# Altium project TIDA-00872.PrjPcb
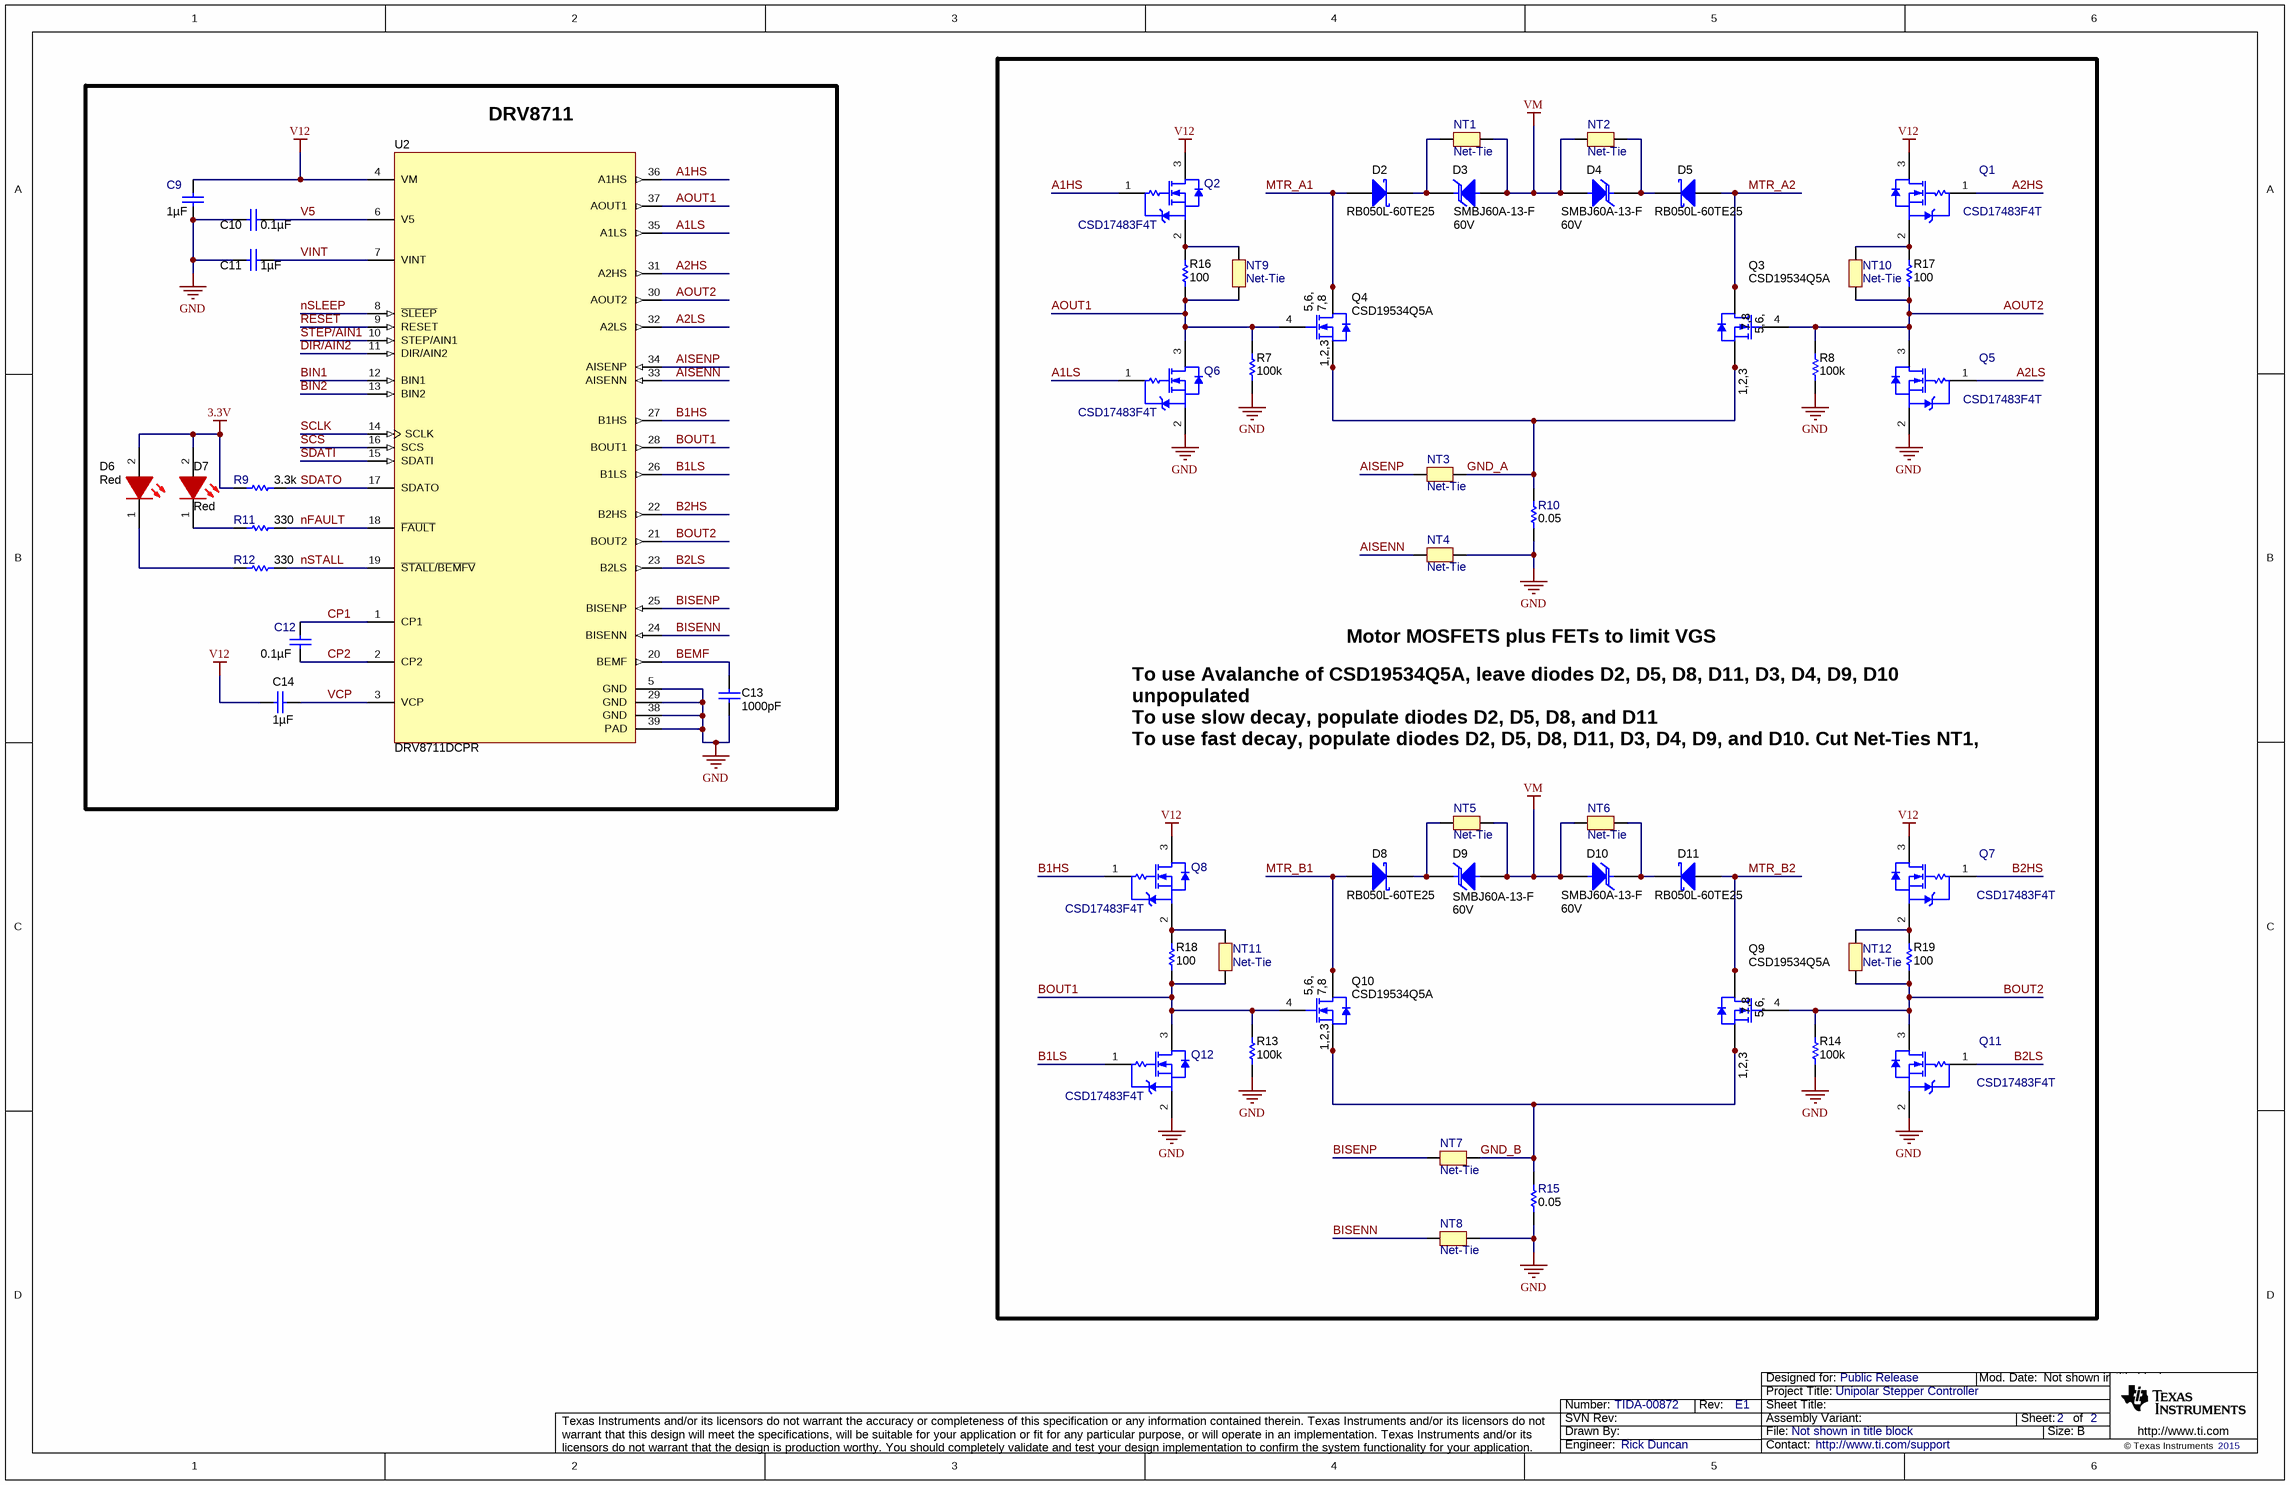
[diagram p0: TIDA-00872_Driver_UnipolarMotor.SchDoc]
CopyrightYear: 2015; EVM_Orderable: N/A; PCB_Layout: Fabio Fernades; PCB_Rev: E1; PRJ_Customer: Public Release; PRJ_Engineer: Rick Duncan; PRJ_Number: TIDA-00872; PRJ_Title: Unipolar Stepper Controller; SCH_Rev: E1; TechSupport: http://www.ti.com/support; TID: TIDA-00872
2 sheets, 82 parts. Net scope: global (net labels, ports and power ports of the same name join across sheets).
Board file: TIDA-00872.PcbDoc
Sheets:
  TIDA-00872_Driver_UnipolarMotor.SchDoc
  TIDA-00872_Unipolar.SchDoc

## Sheet TIDA-00872_Driver_UnipolarMotor.SchDoc
size 431 x 279 mm; Date: Not shown in title block; ApprovedBy: Not shown in title block; CheckedBy: Not shown in title block; Author: Not shown in title block; CompanyName: Not shown in title block; Engineer: Not shown in title block; Organization: Not shown in title block; Address1: Not shown in title block; Address2: Not shown in title block; Address3: Not shown in title block; Address4: Not shown in title block; DocumentNumber: 1; Revision: Use project parameter SCH_Rev; SheetNumber: 2; SheetTotal: 2; PageSetup: Record=PageOptions¦CenterHorizontal=True¦CenterVertical=True¦PrintScale=1.00¦XCorrection=1.00¦YCorrection=1.00¦PrintKind=0¦BorderSize=5000000¦LeftOffset=0¦BottomOffset=0¦Orientation=2¦PaperLength=1000¦PaperWidth=1000¦Scale=100¦PaperSource=15¦PrintQuality=600¦MediaType=1¦DitherType=10¦PaperKind=Letter¦PrintScaleMode=1

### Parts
C9  ValueDisplayed: 1µF  [1206L]  (hidden comment: HMK316B7105KL-T)
C10  ValueDisplayed: 0.1µF  [0603_095]  (hidden comment: 885012206071)
C11  ValueDisplayed: 1µF  [0603_095]  (hidden comment: 885012206052)
C12  ValueDisplayed: 0.1µF  [0603L]  (hidden comment: GRM188R72A104KA35D)
C13  ValueDisplayed: 1000pF  [0603_095]  (hidden comment: 885012206034)
C14  ValueDisplayed: 1µF  [0805_140]  (hidden comment: 885012207103)
D2  RB050L-60TE25  [SMA]
D3  SMBJ60A-13-F  value 60V  [SMB]
D4  SMBJ60A-13-F  value 60V  [SMB]
D5  RB050L-60TE25  [SMA]
D6  value Red  [WL-SMCW_RED_0805]  (hidden comment: 150080SS75000)
D7  value Red  [WL-SMCW_RED_0805]  (hidden comment: 150080SS75000)
D8  RB050L-60TE25  [SMA]
D9  SMBJ60A-13-F  value 60V  [SMB]
D10  SMBJ60A-13-F  value 60V  [SMB]
D11  RB050L-60TE25  [SMA]
NT1  Net-Tie  [Net-Tie_20milWide_60milLong]  (net tie, no BOM)
NT2  Net-Tie  [Net-Tie_20milWide_60milLong]  (net tie, no BOM)
NT3  Net-Tie  [Net-Tie_10mil]  (net tie, no BOM)
NT4  Net-Tie  [Net-Tie_10mil]  (net tie, no BOM)
NT5  Net-Tie  [Net-Tie_20milWide_60milLong]  (net tie, no BOM)
NT6  Net-Tie  [Net-Tie_20milWide_60milLong]  (net tie, no BOM)
NT7  Net-Tie  [Net-Tie_10mil]  (net tie, no BOM)
NT8  Net-Tie  [Net-Tie_10mil]  (net tie, no BOM)
NT9  Net-Tie  [Net-Tie_10mil]  (net tie, no BOM)
NT10  Net-Tie  [Net-Tie_10mil]  (net tie, no BOM)
NT11  Net-Tie  [Net-Tie_10mil]  (net tie, no BOM)
NT12  Net-Tie  [Net-Tie_10mil]  (net tie, no BOM)
Q1  CSD17483F4T  [YJC0003A]
Q2  CSD17483F4T  [YJC0003A]
Q3  CSD19534Q5A  [TRANS_NexFET_Q5A]
Q4  CSD19534Q5A  [TRANS_NexFET_Q5A]
Q5  CSD17483F4T  [YJC0003A]
Q6  CSD17483F4T  [YJC0003A]
Q7  CSD17483F4T  [YJC0003A]
Q8  CSD17483F4T  [YJC0003A]
Q9  CSD19534Q5A  [TRANS_NexFET_Q5A]
Q10  CSD19534Q5A  [TRANS_NexFET_Q5A]
Q11  CSD17483F4T  [YJC0003A]
Q12  CSD17483F4T  [YJC0003A]
R7  ValueDisplayed: 100k  [0402L]  (hidden comment: CRCW0402100KFKED)
R8  ValueDisplayed: 100k  [0402L]  (hidden comment: CRCW0402100KFKED)
R9  value 3.3k  [0603L]  (hidden comment: CRCW06033K30JNEA)
R10  value 0.05  [2512L]  (hidden comment: CRA2512-FZ-R050ELF)
R11  value 330  [0603L]  (hidden comment: CRCW0603330RJNEA)
R12  value 330  [0603L]  (hidden comment: CRCW0603330RJNEA)
R13  ValueDisplayed: 100k  [0402L]  (hidden comment: CRCW0402100KFKED)
R14  ValueDisplayed: 100k  [0402L]  (hidden comment: CRCW0402100KFKED)
R15  value 0.05  [2512L]  (hidden comment: CRA2512-FZ-R050ELF)
R16  ValueDisplayed: 100  [0805L]  (hidden comment: CRCW0805100RFKEA)
R17  ValueDisplayed: 100  [0805L]  (hidden comment: CRCW0805100RFKEA)
R18  ValueDisplayed: 100  [0805L]  (hidden comment: CRCW0805100RFKEA)
R19  ValueDisplayed: 100  [0805L]  (hidden comment: CRCW0805100RFKEA)
U2  DRV8711DCPR  [DCP0038A_N]

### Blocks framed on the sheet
DRV8711: C9-C14 D6 D7 R9 R11 R12 U2
Motor MOSFETS plus FETs to limit VGS: D2-D5 D8-D11 NT1-NT12 Q1-Q12 R7 R8 R10 R13-R19

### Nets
3.3V: D6.2(A) D7.2(A) R9.2
GND: C9.2 C10.2 C11.2 C13.2 NT4.2 NT8.1 Q5.2(S) Q6.2(S) Q11.2(S) Q12.2(S) R7.1 R8.1 R10.1 R13.1 R14.1 R15.1 U2.5(GND) U2.29(GND) U2.38(GND) U2.39(PAD)
V12: C9.1 C14.2 Q1.3(D) Q2.3(D) Q7.3(D) Q8.3(D) U2.4(VM)
VM: D3.2(A) D4.2(A) D9.2(A) D10.2(A) NT1.2 NT2.1 NT5.2 NT6.1
A1HS: Q2.1(G) U2.36(A1HS)
A1LS: Q6.1(G) U2.35(A1LS)
A2HS: Q1.1(G) U2.31(A2HS)
A2LS: Q5.1(G) U2.32(A2LS)
AISENN: NT4.1 U2.33(AISENN)
AISENP: NT3.1 U2.34(AISENP)
AOUT1: NT9.1 Q4.4(G) Q6.3(D) R7.2 R16.1 U2.37(AOUT1)
AOUT2: NT10.1 Q3.4(G) Q5.3(D) R8.2 R17.1 U2.30(AOUT2)
B1HS: Q8.1(G) U2.27(B1HS)
B1LS: Q12.1(G) U2.26(B1LS)
B2HS: Q7.1(G) U2.22(B2HS)
B2LS: Q11.1(G) U2.23(B2LS)
BEMF: C13.1 U2.20(BEMF)
BIN1: U2.12(BIN1)
BIN2: U2.13(BIN2)
BISENN: NT8.2 U2.24(BISENN)
BISENP: NT7.2 U2.25(BISENP)
BOUT1: NT11.1 Q10.4(G) Q12.3(D) R13.2 R18.1 U2.28(BOUT1)
BOUT2: NT12.1 Q9.4(G) Q11.3(D) R14.2 R19.1 U2.21(BOUT2)
CP1: C12.1 U2.1(CP1)
CP2: C12.2 U2.2(CP2)
DIR/AIN2: U2.11(DIR/AIN2)
GND_A: NT3.2 Q3.1(S) Q3.2(S) Q3.3(S) Q4.1(S) Q4.2(S) Q4.3(S) R10.2
GND_B: NT7.1 Q9.1(S) Q9.2(S) Q9.3(S) Q10.1(S) Q10.2(S) Q10.3(S) R15.2
MTR_A1: D2.2(A) Q4.5(D) Q4.6(D) Q4.7(D) Q4.8(D) Q4.9(D)
MTR_A2: D5.2(A) Q3.5(D) Q3.6(D) Q3.7(D) Q3.8(D) Q3.9(D)
MTR_B1: D8.2(A) Q10.5(D) Q10.6(D) Q10.7(D) Q10.8(D) Q10.9(D)
MTR_B2: D11.2(A) Q9.5(D) Q9.6(D) Q9.7(D) Q9.8(D) Q9.9(D)
nFAULT: R11.2 U2.18(~{FAULT})
nSLEEP: U2.8(~{SLEEP})
nSTALL: R12.1 U2.19(~{STALL}/~{BEMFV})
RESET: U2.9(RESET)
SCLK: U2.14(SCLK)
SCS: U2.16(SCS)
SDATI: U2.15(SDATI)
SDATO: R9.1 U2.17(SDATO)
STEP/AIN1: U2.10(STEP/AIN1)
V5: C10.1 U2.6(V5)
VCP: C14.1 U2.3(VCP)
VINT: C11.1 U2.7(VINT)
NetD2_1: D2.1(K) D3.1(K) NT1.1
NetD4_1: D4.1(K) D5.1(K) NT2.2
NetD6_1: D6.1(K) R12.2
NetD7_1: D7.1(K) R11.1
NetD8_1: D8.1(K) D9.1(K) NT5.1
NetD10_1: D10.1(K) D11.1(K) NT6.2
NetNT9_2: NT9.2 Q2.2(S) R16.2
NetNT10_2: NT10.2 Q1.2(S) R17.2
NetNT11_2: NT11.2 Q8.2(S) R18.2
NetNT12_2: NT12.2 Q7.2(S) R19.2

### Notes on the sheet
- To use Avalanche of CSD19534Q5A, leave diodes D2, D5, D8, D11, D3, D4, D9, D10 unpopulated
  To use slow decay, populate diodes D2, D5, D8, and D11
  To use fast decay, populate diodes D2, D5, D8, D11, D3, D4, D9, and D10. Cut Net-Ties NT1, NT2, NT5, and NT6 on bottom of PCB

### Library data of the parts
C9 = GRM31CR72A105KA01L: CAP CER 1UF 100V 10% X7R 1206; Manufacturer: Taiyo Yuden; Polarized: N; CompType: Capacitor; U/M: EA; Cap_F: 0.000001; Tolerance_%: 10; Value1: Unknown; VDC_V: 100; TaMin_C: -55; TaMax_C: 125; Cap_Case: 2220
C10 = 885012206071: CAP, CERM, 0.1 µF, 25 V, +/- 10%, X7R, 0603; Manufacturer: Wurth Elektronik; Polarized: N; CompType: Capacitor; Value: 0.1uF; U/M: EA; Cap_F: 0.0000001; Tolerance_%: 10; Value1: Unknown; VDC_V: 25; Value2: 25V; TaMin_C: -55; TaMax_C: 125; Cap_Case: 0603; AEC Category: Q200
C11 = 885012206052: CAP, CERM, 1 µF, 16 V, +/- 10%, X7R, 0603; Manufacturer: Wurth Elektronik; Polarized: N; CompType: Capacitor; Value: 1uF; U/M: EA; Cap_F: 0.000001; Tolerance_%: 10; Value1: Unknown; VDC_V: 16; Value2: 16V; TaMin_C: -55; TaMax_C: 125; Cap_Case: 0603; AEC Category: Q200
C12 = GRM188R72A104KA35D: CAP, CERM, 0.1uF, 100V, +/-10%, X7R, 0603; Manufacturer: MuRata; Polarized: N; CompType: Capacitor; U/M: EA; Cap_F: 0.0000001; Tolerance_%: 10; Value1: Unknown; VDC_V: 100; TaMin_C: -55; TaMax_C: 125; Cap_Case: 0603
C13 = 885012206034: CAP, CERM, 1000 pF, 16 V, +/- 10%, X7R, 0603; Manufacturer: Wurth Elektronik; Polarized: N; CompType: Capacitor; Value: 1000pF; U/M: EA; Cap_F: 0.000000001; Tolerance_%: 10; Value1: Unknown; VDC_V: 16; Value2: 16V; TaMin_C: -55; TaMax_C: 125; Cap_Case: 0603; AEC Category: Q200
C14 = 885012207103: CAP, CERM, 1 µF, 50 V, +/- 10%, X7R, 0805_140; Manufacturer: Wurth Elektronik; Polarized: N; CompType: Capacitor; Value: 1uF; U/M: EA; Cap_F: 0.000001; Tolerance_%: 10; Value1: Unknown; VDC_V: 50; Value2: 50V; TaMin_C: -55; TaMax_C: 125; Cap_Case: 0805; AEC Category: Q200
D2 D5 D8 D11 = RB050L-60TE25: Diode, Schottky, 60 V, 3 A, SMA; Manufacturer: Rohm; U/M: EA; Vf_V: 0.56; Value: 60V; Value1: 3A; Value2: 0.56V; Io_A: 3; Vr_V: 60; TJmax_C: 150
D3 D4 D9 D10 = SMBJ60A-13-F: Diode, TVS, Uni, 60 V, 600 W, SMB; Manufacturer: Diodes Inc.; U/M: EA; Power_W: 5; Vr_V: 60; Value1: 5W
D6 D7 = 150080SS75000: LED, Red, SMD; Manufacturer: Wurth Elektronik; SymbolCreator: Altium; Type: AlInGaP; Vf_V: 1.9; Value2: 1.9V; Io_A: 0.03; Vr_V: 5; Ir_A: 2.5e-005; Tjmax_C: 85; Power_TotalModule: 0.072; Value1: 0.072W; Angle: 140; U/M: EA
NT1-NT12 = Net-Tie: Single point connection between nets.; SymbolCreator: codlsc
Q1 Q2 Q5-Q8 Q11 Q12 = CSD17483F4T: MOSFET, N/P-CH, 30 V, 1.5 A, 1.0x0.35x0.6mm; Manufacturer: Texas Instruments; Alternate Manufacturer: None; SymbolCreator: a0411947; U/M: EA; ChType: N; Value: 30V; VdsMax_V: 30; Value1: 0.2 ohm; Rdson45_ohm: 0.2; Value2: 1.01 nC; QgTyp_nC: 1.01; Vgs_V: 12; IdsMax_A: 1.5
Q3 Q4 Q9 Q10 = CSD19534Q5A: MOSFET, N-CH, 100 V, 10 A, SON 5x6mm; Manufacturer: Texas Instruments; Alternate Manufacturer: None; U/M: EA; ChType: N; Value: 100V; VdsMax_V: 100; Value1: ? ohm; Value2: 17 nC; QgTyp_nC: 17; Vgs_V: 20; IdsMax_A: 10
R7 R8 R13 R14 = CRCW0402100KFKED: RES, 100 k, 1%, 0.063 W, 0402; Manufacturer: Vishay-Dale; CompType: Resistor; Value: 100k; Res_ohm: 100000; Tolerance_%: 1; Power_W: 0.063; Value2: 0.063W; VDC_V: 50; TempCo: 100 ppm/C; EIA_Code: E96; U/M: EA
R9 = CRCW06033K30JNEA: RES, 3.3k ohm, 5%, 0.1W, 0603; Manufacturer: Vishay-Dale; CompType: Resistor; Res_ohm: 3300; Value_Code: 3k30; Tolerance_%: 5; Power_W: 0.1; VDC_V: 75; TempCo: 200 ppm/C; EIA_Code: E24; U/M: EA
R10 R15 = CRA2512-FZ-R050ELF: RES, 0.05 ohm, 1%, 3W, 2512; Manufacturer: Bourns; CompType: Resistor; Value_Code: R050; Tolerance_%: 1; Power_W: 3; VDC_V: 0; TempCo: 75 ppm/C; EIA_Code: E96; U/M: EA
R11 R12 = CRCW0603330RJNEA: RES, 330 ohm, 5%, 0.1W, 0603; Manufacturer: Vishay-Dale; CompType: Resistor; Value_Code: 330R; Tolerance_%: 5; Power_W: 0.1; VDC_V: 75; TempCo: 200 ppm/C; EIA_Code: E24; U/M: EA
R16-R19 = CRCW0805100RFKEA: RES, 100, 1%, 0.125 W, 0805; Manufacturer: Vishay-Dale; CompType: Resistor; Value: 100; Value_Code: 100R; Tolerance_%: 1; Power_W: 0.125; Value2: 0.125W; VDC_V: 150; TempCo: 100 ppm/C; EIA_Code: E96; U/M: EA
U2 = DRV8711DCPR: STEPPER MOTOR CONTROLLER IC, DCP0038A; Manufacturer: Texas Instruments; SymbolCreator: Altum; U/M: EA

## Sheet TIDA-00872_Unipolar.SchDoc
size A4; Date: Not shown in title block; ApprovedBy: Not shown in title block; CheckedBy: Not shown in title block; Author: Not shown in title block; CompanyName: Not shown in title block; Engineer: Not shown in title block; Organization: Not shown in title block; Address1: Not shown in title block; Address2: Not shown in title block; Address3: Not shown in title block; Address4: Not shown in title block; DocumentNumber: 1; Revision: Use project parameter SCH_Rev; SheetNumber: 1; SheetTotal: 2; PageSetup: Record=PageOptions¦CenterHorizontal=True¦CenterVertical=True¦PrintScale=1.00¦XCorrection=1.00¦YCorrection=1.00¦PrintKind=0¦BorderSize=5000000¦LeftOffset=0¦BottomOffset=0¦Orientation=2¦PaperLength=1000¦PaperWidth=1000¦Scale=100¦PaperSource=15¦PrintQuality=600¦MediaType=1¦DitherType=10¦PaperKind=Letter¦PrintScaleMode=1
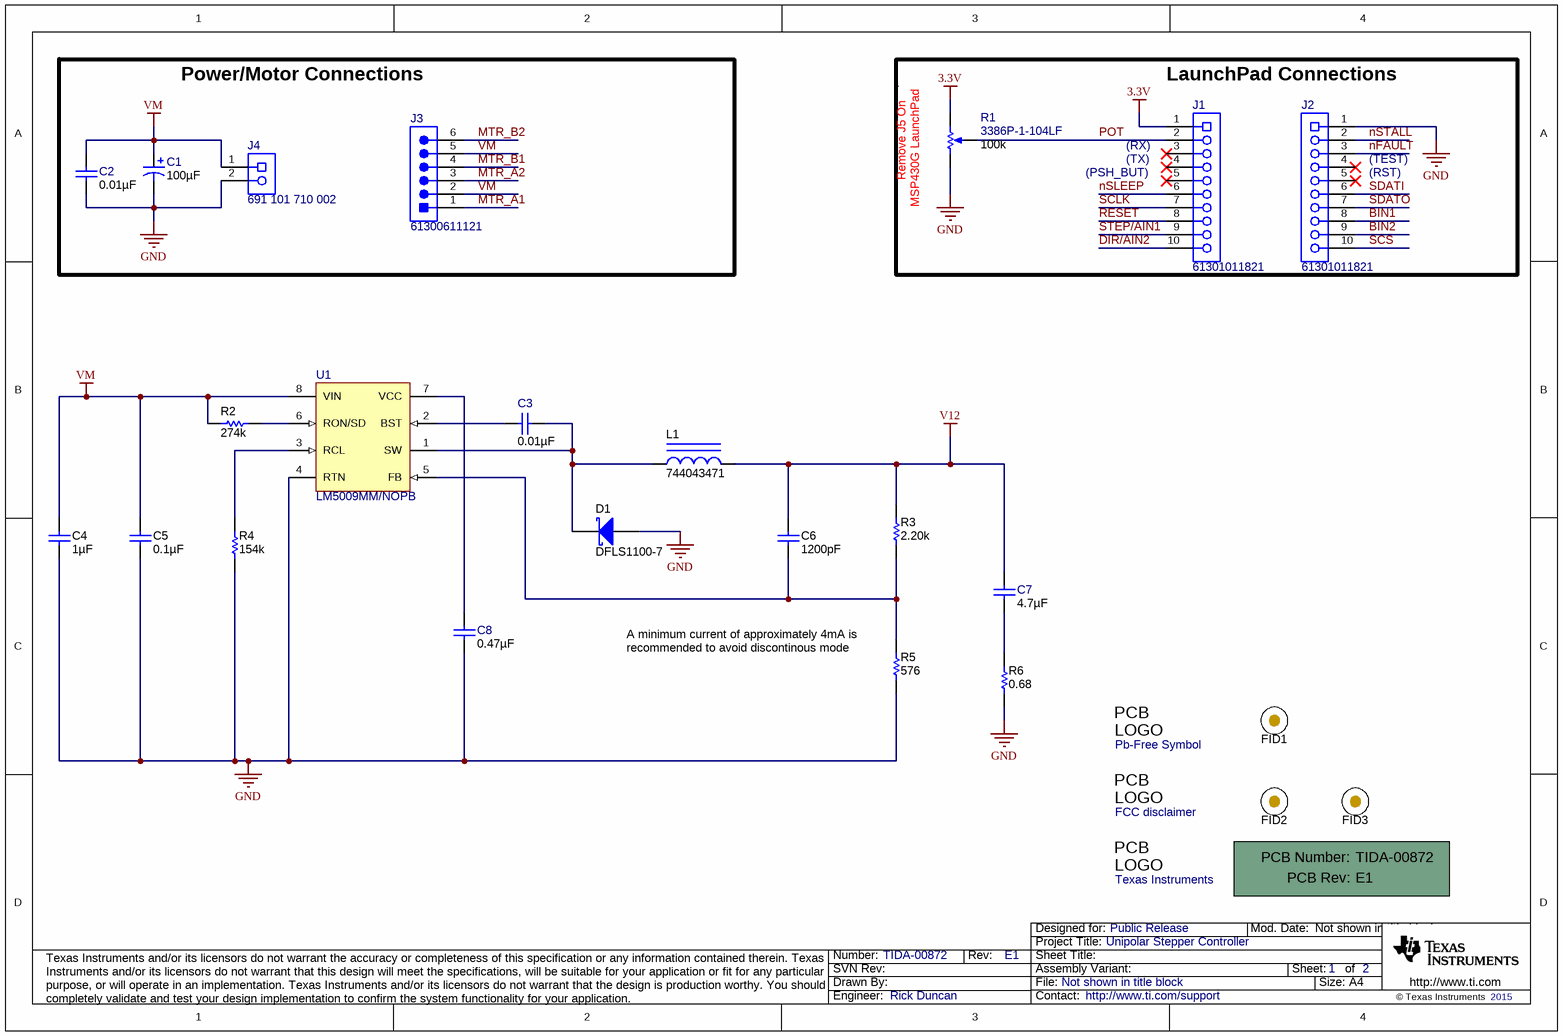
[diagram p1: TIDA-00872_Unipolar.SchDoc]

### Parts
!PCB1  Printed Circuit Board  (value not drawn)  (mechanical)
C1  ValueDisplayed: 100µF  [CAPPR5-10X20]  (hidden comment: ECA-2AM101)
C2  ValueDisplayed: 0.01µF  [0603L]  (hidden comment: C1608X7R2A103K)
C3  ValueDisplayed: 0.01µF  [0402L]  (hidden comment: 885012205031)
C4  ValueDisplayed: 1µF  [1206L]  (hidden comment: C3216X7R2A105M160AA)
C5  ValueDisplayed: 0.1µF  [0805L]  (hidden comment: C2012X7R2A104K125AA)
C6  ValueDisplayed: 1200pF  [1206L]  (hidden comment: C1206C122K5RACTU)
C7  ValueDisplayed: 4.7µF  [0805_145L]  (hidden comment: 885012107013)
C8  ValueDisplayed: 0.47µF  [0805_140]  (hidden comment: 885012207049)
D1  DFLS1100-7  [powerDI123]
FID1  Fiducial  [Fiducial10-20]  (value not drawn)
FID2  Fiducial  [Fiducial10-20]  (value not drawn)
FID3  Fiducial  [Fiducial10-20]  (value not drawn)
J1  61301011821  [Wurth_61301011821]
J2  61301011821  [Wurth_61301011821]
J3  61300611121  [WURTH_61300611121]
J4  691 101 710 002  [Wurth_691101710002]
L1  744043471  [WE-TPC_4828]
Logo1  Pb-Free Symbol  [Pb-Free_Overlay_Medium]  (no BOM)
Logo2  FCC disclaimer  [FCC_disclaimer_stacked]  (no BOM)
Logo3  Texas Instruments  [TI_Symbol_Overlay_Medium]  (no BOM)
R1  3386P-1-104LF  value 100k  [BOURNS_3386P]
R2  ValueDisplayed: 274k  [0402L]  (hidden comment: CRCW0402274KFKED)
R3  ValueDisplayed: 2.20k  [0402L]  (hidden comment: ERJ-2RKF2201X)
R4  ValueDisplayed: 154k  [0402L]  (hidden comment: CRCW0402154KFKED)
R5  ValueDisplayed: 576  [0402L]  (hidden comment: CRCW0402576RFKED)
R6  ValueDisplayed: 0.68  [0402L]  (hidden comment: ERJ-2BQFR68X)
U1  LM5009MM/NOPB  [MUA08A_N]

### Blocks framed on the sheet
Power/Motor Connections: C1 C2 J3 J4

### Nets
3.3V: J1.1 R1.3(CW)
GND: C1.2(-) C2.2 C4.2 C5.2 C8.2 D1.2(A) J2.1 J4.2 R1.1(CCW) R4.1 R5.1 R6.1 U1.4(RTN)
V12: C6.1 C7.1 L1.2 R3.2
VM: C1.1(+) C2.1 C4.1 C5.1 J3.2 J3.5 J4.1 R2.1 U1.8(VIN)
BIN1: J2.8
BIN2: J2.9
DIR/AIN2: J1.10
MTR_A1: J3.1
MTR_A2: J3.3
MTR_B1: J3.4
MTR_B2: J3.6
nFAULT: J2.3
nSLEEP: J1.6
nSTALL: J2.2
POT: J1.2 R1.2(WIPER)
RESET: J1.8
SCLK: J1.7
SCS: J2.10
SDATI: J2.6
SDATO: J2.7
STEP/AIN1: J1.9
NetC3_1: C3.1 U1.2(BST)
NetC3_2: C3.2 D1.1(K) L1.1 U1.1(SW)
NetC6_2: C6.2 R3.1 R5.2 U1.5(FB)
NetC7_2: C7.2 R6.2
NetC8_1: C8.1 U1.7(VCC)
NetR2_2: R2.2 U1.6(RON/SD)
NetR4_2: R4.2 U1.3(RCL)

Not connected (* = marked no-connect by the designer): J1 3* 4* 5*; J2 4* 5*

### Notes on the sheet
- LaunchPad Connections
- (near R1) Remove J5 On
- (near J1) (PSH_BUT)
- (near J1) (RX)
- (near J1) (TX)
- (near J2) (TEST)
- (near J2) (RST)
- (near R1) MSP430G LaunchPad
- (near R5) A minimum current of approximately 4mA is recommended to avoid discontinous mode

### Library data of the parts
!PCB1 = PCB: Manufacturer: Any; PartNumber: TIDA-00872; SymbolCreator: a0412235
C1 = EEV-FK2A101M: CAP ALUM 100UF 100V 20% RADIAL; Manufacturer: Panasonic Electronic Components; Polarized: Y; CompType: Capacitor; U/M: EA; Tolerance_%: 20; VDC_V: 100; TaMin_C: -40; TaMax_C: 85
C2 = C1608X7R2A103K: CAP, CERM, 0.01uF, 100V, +/-10%, X7R, 0603; Manufacturer: TDK; Polarized: N; CompType: Capacitor; U/M: EA; Cap_F: 0.00000001; Tolerance_%: 10; ESR_Ohm: 0.0661; Value1: 0.0661 ohm; VDC_V: 100; TaMin_C: -55; TaMax_C: 125; Cap_Case: 0603
C3 = 885012205031: CAP, CERM, 0.01 µF, 16 V, +/- 10%, X7R, 0402; Manufacturer: Wurth Elektronik; Polarized: N; CompType: Capacitor; Value: 0.01uF; U/M: EA; Cap_F: 0.00000001; Tolerance_%: 10; Value1: Unknown; VDC_V: 16; Value2: 16V; TaMin_C: -55; TaMax_C: 125; Cap_Case: 0402; AEC Category: Q200
C4 = C3216X7R2A105M160AA: CAP, CERM, 1 µF, 100 V, +/- 20%, X7R, 1206; Manufacturer: TDK; Polarized: N; CompType: Capacitor; Value: 1uF; U/M: EA; Cap_F: 0.000001; Tolerance_%: 20; Value1: Unknown; VDC_V: 100; Value2: 100V; TaMin_C: -55; TaMax_C: 125; Cap_Case: 1206
C5 = C2012X7R2A104K125AA: CAP, CERM, 0.1 µF, 100 V, +/- 10%, X7R, 0805; Manufacturer: TDK; Polarized: N; CompType: Capacitor; Value: 0.1uF; U/M: EA; Cap_F: 0.0000001; Tolerance_%: 10; ESR_ohm: 0.0158; Value1: 0.0158 ohm; VDC_V: 100; Value2: 100V; TaMin_C: -55; TaMax_C: 125; Cap_Case: 0805; AEC Category: Q200
C6 = C1206C122K5RACTU: CAP, CERM, 1200 pF, 50 V, +/- 10%, X7R, 1206; Manufacturer: Kemet; Polarized: N; CompType: Capacitor; Value: 1200pF; U/M: EA; Cap_F: 0.0000000012; Tolerance_%: 10; ESR_ohm: 0.604; Value1: 0.604 ohm; VDC_V: 50; Value2: 50V; IRMS_A: 0.164; TaMin_C: -55; TaMax_C: 125; Cap_Case: 1206
C7 = 885012107013: CAP, CERM, 4.7 µF, 16 V, +/- 20%, X5R, 0805; Manufacturer: Wurth Elektronik; Polarized: N; CompType: Capacitor; Value: 4.7uF; U/M: EA; Cap_F: 0.0000047; Tolerance_%: 20; Value1: Unknown; VDC_V: 16; Value2: 16V; TaMin_C: -55; TaMax_C: 85; Cap_Case: 0805; AEC Category: Q200
C8 = 885012207049: CAP, CERM, 0.47 µF, 16 V, +/- 10%, X7R, 0805_140; Manufacturer: Wurth Elektronik; Polarized: N; CompType: Capacitor; Value: 0.47uF; U/M: EA; Cap_F: 0.00000047; Tolerance_%: 10; Value1: Unknown; VDC_V: 16; Value2: 16V; TaMin_C: -55; TaMax_C: 125; Cap_Case: 0805; AEC Category: Q200
D1 = DFLS1100-7: Diode, Schottky, 100 V, 1 A, PowerDI123; Manufacturer: Diodes Inc.; U/M: EA; Vf_V: 0.77; Value: 100V; Value1: 1A; Value2: 0.77V; Io_A: 1; Vr_V: 100; TJmax_C: 175; RJC_CperW: 7
FID1-FID3 = Fiducial: Fiducial mark.  There is nothing to buy or mount.; SymbolCreator: codlsc
J1 J2 = 61301011821: Receptacle, 2.54mm, 10x1, Gold, TH; Manufacturer: Wurth Elektronik; SymbolCreator: a0411947; U/M: EA
J3 = 61300611121: Header, 2.54 mm, 6x1, Gold, TH; Manufacturer: Wurth Elektronik; SymbolCreator: a0412235; U/M: EA
J4 = 691 101 710 002: Terminal Block, 5 mm, 2x1, Tin, TH; Manufacturer: Wurth Elektronik; SymbolCreator: a0412235; U/M: EA
L1 = 744043471: Inductor, Shielded Drum Core, Metal Composite, 470 µH, 0.125 A, 2.128 ohm, SMD; Manufacturer: Wurth Elektronik; Value: 470uH; Ind_H: 470.0E-6; ValueDisplayed: 470µH; Imax_A: 0.125; Irms: 0.24A @ 30C rise; Isat: 0.125A @ 35% inductance drop; DCR_ohm: 2.128; Value2: 0.125A
Logo1 = Pb-Free: SymbolCreator: a0412235
Logo2 = FCC_disclaimer: SymbolCreator: codlsc
Logo3 = TI_Logo: Texas Instrument Corporate Signature; SymbolCreator: a0412235
R1 = 3386P-1-104LF: TRIMMER, 100k ohm, 0.5W, TH; Manufacturer: Bourns; Sim Note: Enter the Resistance value and the set point into parameter fields.; SymbolCreator: a0412235
R2 = CRCW0402274KFKED: RES, 274 k, 1%, 0.063 W, 0402; Manufacturer: Vishay-Dale; CompType: Resistor; Value: 274k; Res_ohm: 274000; Tolerance_%: 1; Power_W: 0.063; Value2: 0.063W; VDC_V: 50; TempCo: 100 ppm/C; EIA_Code: E96; U/M: EA
R3 = ERJ-2RKF2201X: RES, 2.20 k, 1%, 0.1 W, 0402; Manufacturer: Panasonic; CompType: Resistor; Value: 2.20k; Res_ohm: 2200; Value_Code: 2k20; Tolerance_%: 1; Power_W: 0.1; Value2: 0.1W; VDC_V: 50; TempCo: 100 ppm/C; U/M: EA; AEC Category: Q200
R4 = CRCW0402154KFKED: RES, 154 k, 1%, 0.063 W, 0402; Manufacturer: Vishay-Dale; CompType: Resistor; Value: 154k; Res_ohm: 154000; Tolerance_%: 1; Power_W: 0.063; Value2: 0.063W; VDC_V: 50; TempCo: 100 ppm/C; EIA_Code: E96; U/M: EA
R5 = CRCW0402576RFKED: RES, 576, 1%, 0.063 W, 0402; Manufacturer: Vishay-Dale; CompType: Resistor; Value: 576; Value_Code: 576R; Tolerance_%: 1; Power_W: 0.063; Value2: 0.063W; VDC_V: 50; TempCo: 100 ppm/C; EIA_Code: E96; U/M: EA; AEC Category: Q200
R6 = ERJ-2BQFR68X: RES, 0.68, 1%, 0.125 W, 0402; Manufacturer: Panasonic; CompType: Resistor; Value: 0.68; Value_Code: R680; Tolerance_%: 1; Power_W: 0.125; Value2: 0.125W; TempCo: 250 ppm/C; EIA_Code: E96; U/M: EA
U1 = LM5009MM/NOPB: 150 mA, 100V Step-Down Switching Regulator, 8-pin MSOP, Pb-Free; Manufacturer: Texas Instruments; PackageTopMarking: ZXTT*SLLB; PowerWise: Y; CompType: Switcher

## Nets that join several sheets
3.3V: TIDA-00872_Driver_UnipolarMotor (D6.2 D7.2 R9.2), TIDA-00872_Unipolar (J1.1 R1.3)
GND: TIDA-00872_Driver_UnipolarMotor (20 pins), TIDA-00872_Unipolar (13 pins)
V12: TIDA-00872_Driver_UnipolarMotor (7 pins), TIDA-00872_Unipolar (C6.1 C7.1 L1.2 R3.2)
VM: TIDA-00872_Driver_UnipolarMotor (8 pins), TIDA-00872_Unipolar (9 pins)
BIN1: TIDA-00872_Driver_UnipolarMotor (U2.12), TIDA-00872_Unipolar (J2.8)
BIN2: TIDA-00872_Driver_UnipolarMotor (U2.13), TIDA-00872_Unipolar (J2.9)
DIR/AIN2: TIDA-00872_Driver_UnipolarMotor (U2.11), TIDA-00872_Unipolar (J1.10)
MTR_A1: TIDA-00872_Driver_UnipolarMotor (6 pins), TIDA-00872_Unipolar (J3.1)
MTR_A2: TIDA-00872_Driver_UnipolarMotor (6 pins), TIDA-00872_Unipolar (J3.3)
MTR_B1: TIDA-00872_Driver_UnipolarMotor (6 pins), TIDA-00872_Unipolar (J3.4)
MTR_B2: TIDA-00872_Driver_UnipolarMotor (6 pins), TIDA-00872_Unipolar (J3.6)
nFAULT: TIDA-00872_Driver_UnipolarMotor (R11.2 U2.18), TIDA-00872_Unipolar (J2.3)
nSLEEP: TIDA-00872_Driver_UnipolarMotor (U2.8), TIDA-00872_Unipolar (J1.6)
nSTALL: TIDA-00872_Driver_UnipolarMotor (R12.1 U2.19), TIDA-00872_Unipolar (J2.2)
RESET: TIDA-00872_Driver_UnipolarMotor (U2.9), TIDA-00872_Unipolar (J1.8)
SCLK: TIDA-00872_Driver_UnipolarMotor (U2.14), TIDA-00872_Unipolar (J1.7)
SCS: TIDA-00872_Driver_UnipolarMotor (U2.16), TIDA-00872_Unipolar (J2.10)
SDATI: TIDA-00872_Driver_UnipolarMotor (U2.15), TIDA-00872_Unipolar (J2.6)
SDATO: TIDA-00872_Driver_UnipolarMotor (R9.1 U2.17), TIDA-00872_Unipolar (J2.7)
STEP/AIN1: TIDA-00872_Driver_UnipolarMotor (U2.10), TIDA-00872_Unipolar (J1.9)

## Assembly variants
001: not fitted D2 D3 D4 D5 D8 D9 D10 D11 FID1 FID2 FID3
